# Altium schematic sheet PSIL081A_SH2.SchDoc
size 558 x 431 mm; Date: Not shown in title block; ApprovedBy: Not shown in title block; CheckedBy: Not shown in title block; Author: Not shown in title block; CompanyName: Not shown in title block; Engineer: Not shown in title block; Organization: Not shown in title block; Address1: Not shown in title block; Address2: Not shown in title block; Address3: Not shown in title block; Address4: Not shown in title block; DocumentNumber: 2; Revision: Use project parameter SCH_Rev; SheetNumber: 2; SheetTotal: 5; PageSetup: Record=PageOptions¦CenterHorizontal=True¦CenterVertical=True¦PrintScale=1.00¦XCorrection=1.00¦YCorrection=1.00¦PrintKind=0¦BorderSize=5000000¦LeftOffset=0¦BottomOffset=0¦Orientation=2¦PaperLength=1000¦PaperWidth=1000¦Scale=100¦PaperSource=15¦PrintQuality=600¦MediaType=1¦DitherType=10¦PaperKind=Letter¦PrintScaleMode=1
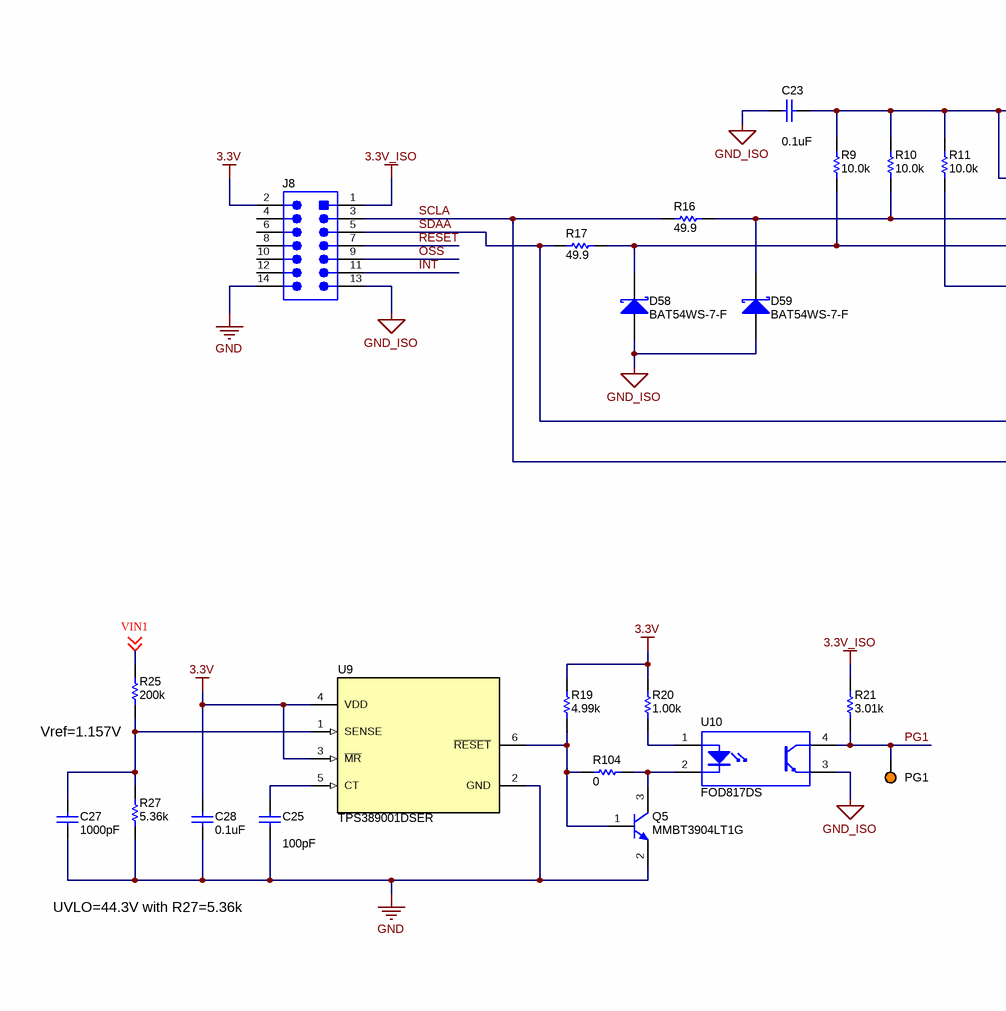
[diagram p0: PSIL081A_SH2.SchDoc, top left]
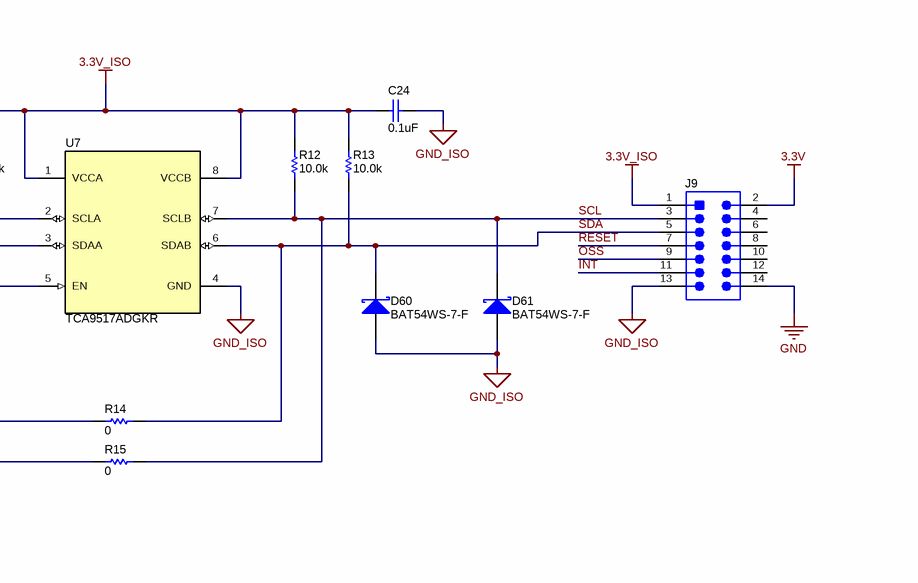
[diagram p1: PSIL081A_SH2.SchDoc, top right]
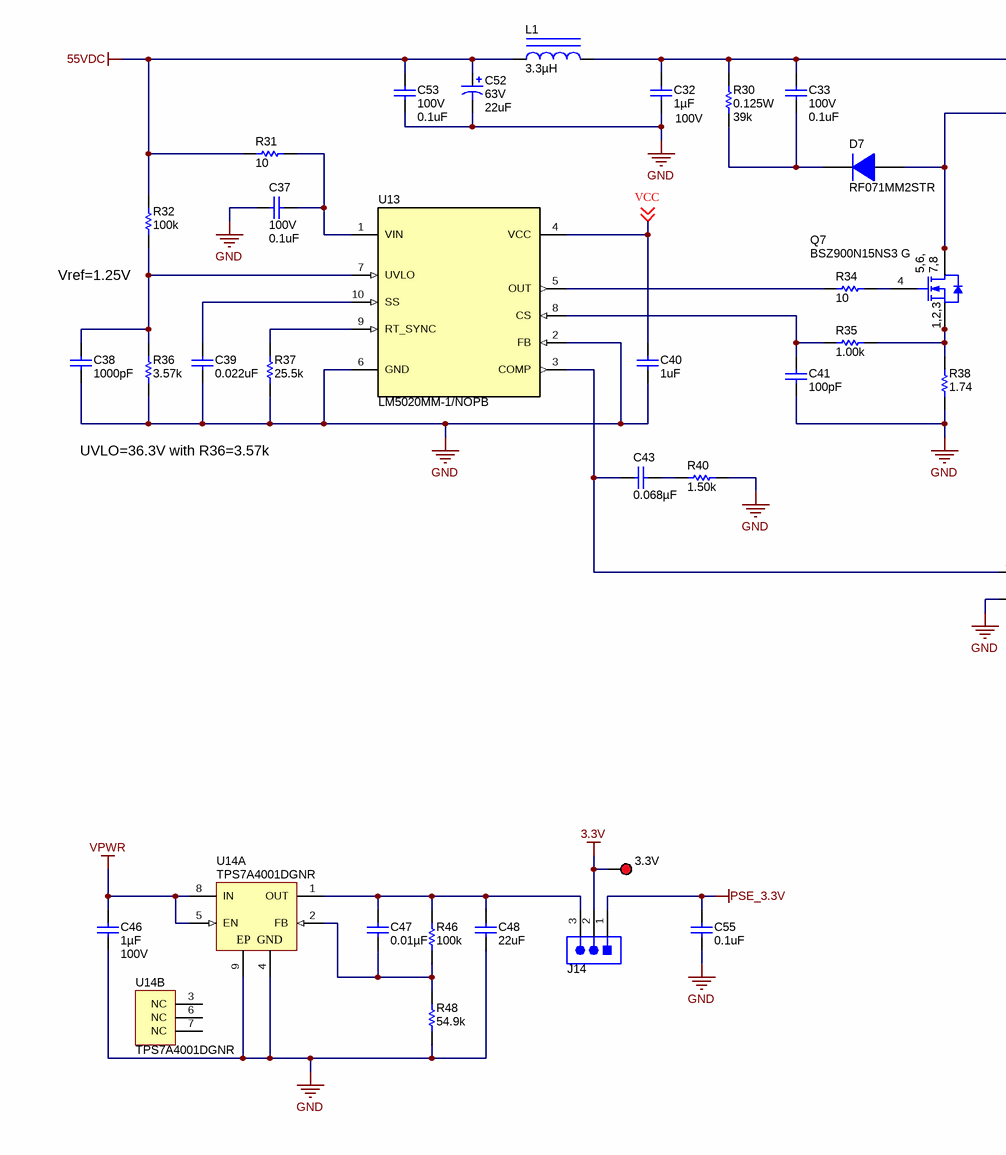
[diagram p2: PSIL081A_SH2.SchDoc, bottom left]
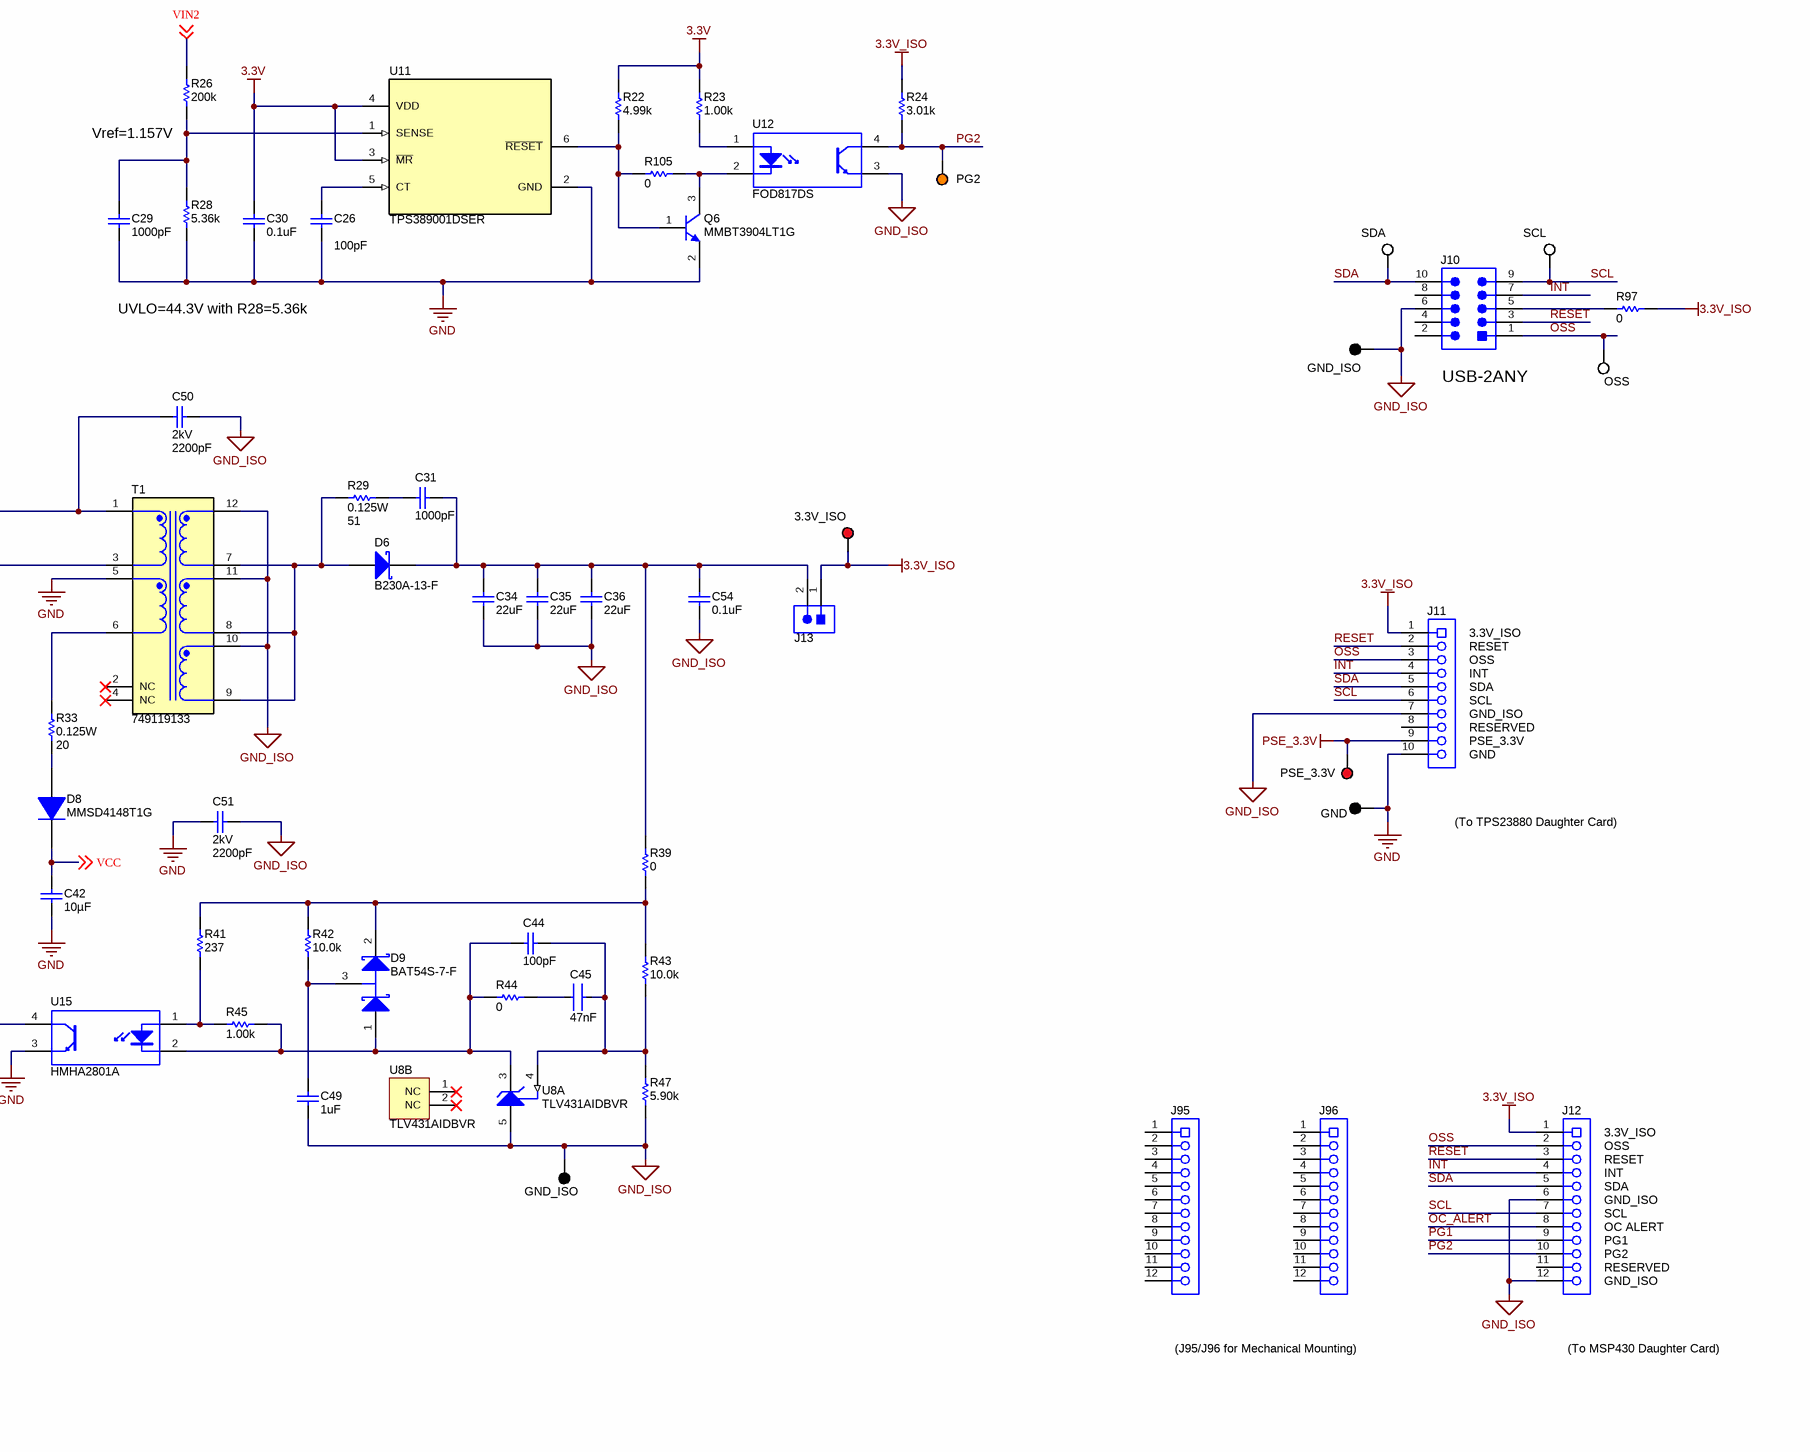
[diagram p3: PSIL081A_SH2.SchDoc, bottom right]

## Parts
C23  ValueDisplayed: 0.1uF  [0603]  (hidden comment: 885012206046)
C24  ValueDisplayed: 0.1uF  [0603]  (hidden comment: 885012206046)
C25  ValueDisplayed: 100pF  [0603]  (hidden comment: 885012006057)
C26  ValueDisplayed: 100pF  [0603]  (hidden comment: 885012006057)
C27  ValueDisplayed: 1000pF  [0402]  (hidden comment: 885012205044)
C28  ValueDisplayed: 0.1uF  [0603]  (hidden comment: 885012206046)
C29  ValueDisplayed: 1000pF  [0402]  (hidden comment: 885012205044)
C30  ValueDisplayed: 0.1uF  [0603]  (hidden comment: 885012206046)
C31  ValueDisplayed: 1000pF  [0603]  (hidden comment: 885012206083)
C32  ValueDisplayed: 1µF  VDC_V: 100V  [1206]  (hidden comment: 12061C105KAT2A)
C33  VDC_V: 100V  ValueDisplayed: 0.1uF  [0805_HV]  (hidden comment: C2012X7R2A104K125AA)
C34  ValueDisplayed: 22uF  [1206]  (hidden comment: JMK316BJ226ML-T)
C35  ValueDisplayed: 22uF  [1206]  (hidden comment: JMK316BJ226ML-T)
C36  ValueDisplayed: 22uF  [1206]  (hidden comment: JMK316BJ226ML-T)
C37  VDC_V: 100V  ValueDisplayed: 0.1uF  [0805_HV]  (hidden comment: C2012X7R2A104K125AA)
C38  ValueDisplayed: 1000pF  [0402]  (hidden comment: 885012205044)
C39  ValueDisplayed: 0.022uF  [0603]  (hidden comment: 885012206091)
C40  ValueDisplayed: 1uF  [0603]  (hidden comment: 885012206052)
C41  ValueDisplayed: 100pF  [0402]  (hidden comment: 885012005061)
C42  ValueDisplayed: 10µF  [1206]  (hidden comment: 885012208041)
C43  ValueDisplayed: 0.068µF  [0603]  (hidden comment: 885012206070)
C44  ValueDisplayed: 100pF  [0402]  (hidden comment: 885012005061)
C45  Cap_F: 47nF  [FP-885012206069_0603-MFG]  (hidden comment: 885012206069)
C46  ValueDisplayed: 1µF  VDC_V: 100V  [1206]  (hidden comment: 12061C105KAT2A)
C47  ValueDisplayed: 0.01µF  [0603]  (hidden comment: 885012206089)
C48  ValueDisplayed: 22uF  [1206]  (hidden comment: JMK316BJ226ML-T)
C49  ValueDisplayed: 1uF  [0603]  (hidden comment: 885012206052)
C50  VDC_V: 2kV  ValueDisplayed: 2200pF  [1812_HV]  (hidden comment: C4532X7R3D222K130KA)
C51  VDC_V: 2kV  ValueDisplayed: 2200pF  [1812_HV]  (hidden comment: C4532X7R3D222K130KA)
C52  VDC_V: 63V  ValueDisplayed: 22uF  [SM_RADIAL_E]  (hidden comment: EEE-FK1J220P)
C53  VDC_V: 100V  ValueDisplayed: 0.1uF  [0805_HV]  (hidden comment: C2012X7R2A104K125AA)
C54  ValueDisplayed: 0.1uF  [0603]  (hidden comment: 885012206046)
C55  ValueDisplayed: 0.1uF  [0603]  (hidden comment: 885012206046)
D6  B230A-13-F  [SMA]
D7  RF071MM2STR  [SOD-123F]
D8  MMSD4148T1G  [SOD-123]
D9  BAT54S-7-F  [SOT-23]
D58  BAT54WS-7-F  [SOD-323]
D59  BAT54WS-7-F  [SOD-323]
D60  BAT54WS-7-F  [SOD-323]
D61  BAT54WS-7-F  [SOD-323]
J8  TST-107-01-G-D  [Samtec_TST-107-01-G-D]  (value not drawn)
J9  TST-107-01-G-D  [Samtec_TST-107-01-G-D]  (value not drawn)
J10  N2510-6002-RB  [CONN_2510-6002]  (value not drawn)
J11  SSW-110-21-G-S  [CONN_SSW-110-23-F-S]  (value not drawn)
J12  SSW-112-21-G-S  [Samtec_SSW-112-21-x-S]  (value not drawn)
J13  TSW-102-07-G-S  [TSW-102-07-G-S]  (value not drawn)
J14  TSW-103-07-G-S  [TSW-103-07-G-S]  (value not drawn)
J95  SSW-112-21-G-S  [Samtec_SSW-112-21-x-S]  (value not drawn)
J96  SSW-112-21-G-S  [Samtec_SSW-112-21-x-S]  (value not drawn)
L1  ValueDisplayed: 3.3µH  [WE-MAPI_2510]  (hidden comment: 74438323033)
Q5  MMBT3904LT1G  [SOT-23]
Q6  MMBT3904LT1G  [SOT-23]
Q7  BSZ900N15NS3 G  [PG-TSDSON-8]
R9  ValueDisplayed: 10.0k  [0402]  (hidden comment: CRCW040210K0FKED)
R10  ValueDisplayed: 10.0k  [0402]  (hidden comment: CRCW040210K0FKED)
R11  ValueDisplayed: 10.0k  [0402]  (hidden comment: CRCW040210K0FKED)
R12  ValueDisplayed: 10.0k  [0402]  (hidden comment: CRCW040210K0FKED)
R13  ValueDisplayed: 10.0k  [0402]  (hidden comment: CRCW040210K0FKED)
R14  ValueDisplayed: 0  [0402]  (hidden comment: ERJ-2GE0R00X)
R15  ValueDisplayed: 0  [0402]  (hidden comment: ERJ-2GE0R00X)
R16  ValueDisplayed: 49.9  [0402]  (hidden comment: CRCW040249R9FKED)
R17  ValueDisplayed: 49.9  [0402]  (hidden comment: CRCW040249R9FKED)
R19  ValueDisplayed: 4.99k  [0402]  (hidden comment: CRCW04024K99FKED)
R20  ValueDisplayed: 1.00k  [0402]  (hidden comment: CRCW04021K00FKED)
R21  ValueDisplayed: 3.01k  [0402]  (hidden comment: CRCW04023K01FKED)
R22  ValueDisplayed: 4.99k  [0402]  (hidden comment: CRCW04024K99FKED)
R23  ValueDisplayed: 1.00k  [0402]  (hidden comment: CRCW04021K00FKED)
R24  ValueDisplayed: 3.01k  [0402]  (hidden comment: CRCW04023K01FKED)
R25  ValueDisplayed: 200k  [0402]  (hidden comment: CRCW0402200KFKED)
R26  ValueDisplayed: 200k  [0402]  (hidden comment: CRCW0402200KFKED)
R27  ValueDisplayed: 5.36k  [0402]  (hidden comment: CRCW04025K36FKED)
R28  ValueDisplayed: 5.36k  [0402]  (hidden comment: CRCW04025K36FKED)
R29  Value2: 0.125W  ValueDisplayed: 51  [0805_HV]  (hidden comment: CRCW080551R0JNEA)
R30  Value2: 0.125W  ValueDisplayed: 39k  [0805_HV]  (hidden comment: CRCW080539K0JNEA)
R31  ValueDisplayed: 10  [0402]  (hidden comment: CRCW040210R0JNED)
R32  ValueDisplayed: 100k  [0402]  (hidden comment: CRCW0402100KFKED)
R33  Value2: 0.125W  ValueDisplayed: 20  [0805_HV]  (hidden comment: CRCW080520R0JNEA)
R34  ValueDisplayed: 10  [0402]  (hidden comment: CRCW040210R0JNED)
R35  ValueDisplayed: 1.00k  [0402]  (hidden comment: CRCW04021K00FKED)
R36  ValueDisplayed: 3.57k  [0402]  (hidden comment: CRCW04023K57FKED)
R37  ValueDisplayed: 25.5k  [0402]  (hidden comment: CRCW040225K5FKED)
R38  ValueDisplayed: 1.74  [0603]  (hidden comment: CRCW06031R74FKEA)
R39  ValueDisplayed: 0  [0402]  (hidden comment: ERJ-2GE0R00X)
R40  ValueDisplayed: 1.50k  [0402]  (hidden comment: CRCW04021K50FKED)
R41  ValueDisplayed: 237  [0402]  (hidden comment: CRCW0402237RFKED)
R42  ValueDisplayed: 10.0k  [0402]  (hidden comment: CRCW040210K0FKED)
R43  ValueDisplayed: 10.0k  [0402]  (hidden comment: CRCW040210K0FKED)
R44  ValueDisplayed: 0  [0402]  (hidden comment: ERJ-2GE0R00X)
R45  ValueDisplayed: 1.00k  [0402]  (hidden comment: CRCW04021K00FKED)
R46  ValueDisplayed: 100k  [0402]  (hidden comment: CRCW0402100KFKED)
R47  ValueDisplayed: 5.90k  [0402]  (hidden comment: CRCW04025K90FKED)
R48  ValueDisplayed: 54.9k  [0402]  (hidden comment: CRCW040254K9FKED)
R97  ValueDisplayed: 0  [0402]  (hidden comment: ERJ-2GE0R00X)
R104  ValueDisplayed: 0  [0402]  (hidden comment: ERJ-2GE0R00X)
R105  ValueDisplayed: 0  [0402]  (hidden comment: ERJ-2GE0R00X)
T1  749119133  [Wurth_EP11_5]
TP4  SDA  [Keystone5002]
TP5  SCL  [Keystone5002]
TP6  PG1  [Keystone5003]
TP7  PG2  [Keystone5003]
TP8  PSE_3.3V  [Keystone5000]
TP9  GND  [Keystone5001]
TP10  3.3V_ISO  [Keystone5000]
TP11  3.3V  [Keystone5000]
TP12  GND_ISO  [Keystone5001]
TP13  GND_ISO  [Keystone5001]
TP14  OSS  [Keystone5002]
U7  TCA9517ADGKR  [DGK0008A_N]
U8  TLV431AIDBVR  [DBV0005A_N]  (parts A,B of 2)
U9  TPS389001DSER  [DSE0006A]
U10  FOD817DS  [N04C]
U11  TPS389001DSER  [DSE0006A]
U12  FOD817DS  [N04C]
U13  LM5020MM-1/NOPB  [DGS0010A_N]
U14  TPS7A4001DGNR  [DGN0008B_N]  (parts A,B of 2)
U15  HMHA2801A  [MFP04A]

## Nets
3.3V: C28.2 C30.2 J8.2 J9.2 J14.2 R19.1 R20.1 R22.1 R23.1 TP11.1 U9.3(~{MR}) U9.4(VDD) U11.3(~{MR}) U11.4(VDD)
3.3V_ISO: C23.1 C24.1 J8.1 J9.1 J11.1 J12.1 J13.1 R9.1 R10.1 R11.1 R12.1 R13.1 R21.1 R24.1 R97.1 TP10.1 U7.1(VCCA) U7.8(VCCB)
55VDC: C52.1(+) C53.2 L1.1 R31.1 R32.1
GND: C25.1 C26.1 C27.1 C28.1 C29.1 C30.1 C32.1 C37.2 C38.1 C39.1 C40.1 C41.1 C42.1 C46.2 C48.2 C51.2 C52.2(-) C53.1 C55.1 J8.14 J9.14 J11.10 Q5.2(E) Q6.2(E) R27.2 R28.2 R36.2 R37.2 R38.2 R40.2 R48.2 T1.5 TP9.1 U9.2(GND) U11.2(GND) U13.2(FB) U13.6(GND) U14.4(GND) U14.9(EP) U15.3(E)
GND_ISO: C23.2 C24.2 C34.1 C35.1 C36.1 C49.1 C50.1 C51.1 C54.1 D58.2(A) D59.2(A) D60.2(A) D61.2(A) J8.13 J9.13 J10.6 J11.7 J12.6 J12.12 R47.2 T1.10 T1.11 T1.12 TP12.1 TP13.1 U7.4(GND) U8.5(ANODE) U10.3(E) U12.3(E)
PSE_3.3V: C55.2 J11.9 J14.1 TP8.1
VPWR: C46.1 U14.5(EN) U14.8(IN)
INT: J8.11 J9.11 J10.7 J11.4 J12.4
OC_ALERT: J12.8
OSS: J8.9 J9.9 J10.1 J11.3 J12.2 TP14.1
PG1: J12.9 R21.2 TP6.1 U10.4(C)
PG2: J12.10 R24.2 TP7.1 U12.4(C)
RESET: J8.7 J9.7 J10.3 J11.2 J12.3
SCL: D61.1(K) J9.3 J10.9 J11.6 J12.7 R12.2 R15.1 TP5.1 U7.7(SCLB)
SCLA: J8.3 R15.2 R16.1
SDA: D60.1(K) J9.5 J10.10 J11.5 J12.5 R13.2 R14.1 TP4.1 U7.6(SDAB)
SDAA: J8.5 R14.2 R17.1
VCC: C40.2 C42.2 D8.1(K) U13.4(VCC) ; off-sheet VCC
VIN1: R25.1 ; off-sheet VIN1
VIN2: R26.1 ; off-sheet VIN2
NetC25_2: C25.2 U9.5(CT)
NetC26_2: C26.2 U11.5(CT)
NetC27_2: C27.2 R25.2 R27.1 U9.1(SENSE)
NetC29_2: C29.2 R26.2 R28.1 U11.1(SENSE)
NetC31_1: C31.1 C34.2 C35.2 C36.2 C54.2 D6.1(K) J13.2 R39.2
NetC31_2: C31.2 R29.2
NetC32_2: C32.2 C33.2 C50.2 L1.2 R30.1 T1.1
NetC33_1: C33.1 D7.1(K) R30.2
NetC37_1: C37.1 R31.2 U13.1(VIN)
NetC38_2: C38.2 R32.2 R36.1 U13.7(UVLO)
NetC39_2: C39.2 U13.10(SS)
NetC41_2: C41.2 R35.1 U13.8(CS)
NetC43_1: C43.1 R40.1
NetC43_2: C43.2 U13.3(COMP) U15.4(C)
NetC44_1: C44.1 C45.1 R43.2 R47.1 U8.4(REF)
NetC44_2: C44.2 D9.1(A) R44.2 R45.1 U8.3(CATHODE) U15.2(K)
NetC45_2: C45.2 R44.1
NetC47_1: C47.1 C48.1 J14.3 R46.1 U14.1(OUT)
NetC47_2: C47.2 R46.2 R48.1 U14.2(FB)
NetC49_2: C49.2 D9.3(C) R42.2
NetD6_2: D6.2(A) R29.1 T1.7 T1.8 T1.9
NetD7_2: D7.2(A) Q7.5(D) Q7.6(D) Q7.7(D) Q7.8(D) Q7.9(D) T1.3
NetD8_2: D8.2(A) R33.2
NetD9_2: D9.2(K) R39.1 R41.1 R42.1 R43.1
NetD58_1: D58.1(K) R9.2 R17.2 U7.3(SDAA)
NetD59_1: D59.1(K) R10.2 R16.2 U7.2(SCLA)
NetJ10_5: J10.5 R97.2
NetQ5_1: Q5.1(B) R19.2 R104.2 U9.6(~{RESET})
NetQ5_3: Q5.3(C) R104.1 U10.2(K)
NetQ6_1: Q6.1(B) R22.2 R105.2 U11.6(~{RESET})
NetQ6_3: Q6.3(C) R105.1 U12.2(K)
NetQ7_1: Q7.1(S) Q7.2(S) Q7.3(S) R35.2 R38.1
NetQ7_4: Q7.4(G) R34.2
NetR11_2: R11.2 U7.5(EN)
NetR20_2: R20.2 U10.1(A)
NetR23_2: R23.2 U12.1(A)
NetR33_1: R33.1 T1.6
NetR34_1: R34.1 U13.5(OUT)
NetR37_1: R37.1 U13.9(RT_SYNC)
NetR41_2: R41.2 R45.2 U15.1(A)

Not connected (* = marked no-connect by the designer): J8 4 6 8 10 12; J9 4 6 8 10 12; J10 2 4 8; J11 8; J12 11; J95 1 2 3 4 5 6 7 8 9 10 11 12; J96 1 2 3 4 5 6 7 8 9 10 11 12; T1 2(NC)* 4(NC)*; U8 1(NC)* 2(NC)*; U14 3(NC) 6(NC) 7(NC)

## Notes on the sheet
- (near R25) Vref=1.157V
- (near R26) Vref=1.157V
- UVLO=44.3V with R27=5.36k
- UVLO=44.3V with R28=5.36k
- (near J10) USB-2ANY
- (near J11) 3.3V_ISO
- (near J11) RESET
- (near J11) OSS
- (near J11) INT
- (near J11) SDA
- (near J11) SCL
- (near R32) Vref=1.25V
- (near J11) RESERVED
- (near J11) GND_ISO
- (near J11) PSE_3.3V
- (near J11) GND
- (To TPS23880 Daughter Card)
- UVLO=36.3V with R36=3.57k
- (near J12) 3.3V_ISO
- (near J12) OSS
- (near J12) RESET
- (near J12) INT
- (near J12) SDA
- (near J12) GND_ISO
- (near J12) SCL
- (near J12) OC ALERT
- (near J12) PG1
- (near J12) PG2
- (near J12) RESERVED
- (J95/J96 for Mechanical Mounting)
- (To MSP430 Daughter Card)

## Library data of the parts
C23 C24 C28 C30 C54 C55 = CMP-0006829-4: CAP, CERM, 0.1 uF, 16 V, +/- 10%, X7R, 0603; Manufacturer: Wurth Elektronik; TaMin_C: -55°C; Polarized: N; SizeAreaWB_mm2: 4.68; Value1: Unknown; U/M: EA; Value: 0.1uF; TaMax_C: 125°C; SizeZ_mm: 1; SizeX_mm: 1.6; SizeY_mm: 0.8; Value2: 16V; SizeArea_mm2: 1.28; CompType: Capacitor; Cap_F: 100nF; AEC Category: Q200
C25 C26 = CMP-0006822-4: CAP, CERM, 100 pF, 50 V, +/- 5%, C0G/NP0, 0603; Manufacturer: Wurth Elektronik; TaMin_C: -55°C; Polarized: N; SizeAreaWB_mm2: 4.68; Value1: Unknown; U/M: EA; Value: 100pF; TaMax_C: 125°C; SizeZ_mm: 1; SizeX_mm: 1.6; SizeY_mm: 0.8; Value2: 50V; SizeArea_mm2: 1.28; CompType: Capacitor; AEC Category: Q200
C27 C29 C38 = CMP-0006229-2: CAP, CERM, 1000 pF, 25 V, +/- 10%, X7R, 0402; Manufacturer: Wurth Elektronik; TaMin_C: -55°C; Polarized: N; SizeAreaWB_mm2: 3; Value1: Unknown; U/M: EA; Value: 1000pF; TaMax_C: 125°C; SizeZ_mm: 0.6; SizeX_mm: 1; SizeY_mm: 0.5; Value2: 25V; CompType: Capacitor; Cap_F: 1nF; AEC Category: Q200
C31 = CMP-0064933-4: CAP, CERM, 1000 pF, 50 V,+/- 10%, X7R, 0603; Manufacturer: Wurth Elektronik; TaMin_C: -55°C; Polarized: N; SizeAreaWB_mm2: 4.68; Value1: Unknown; U/M: EA; Value: 1000pF; TaMax_C: 125°C; SizeZ_mm: 1; SizeX_mm: 1.6; SizeY_mm: 0.8; Value2: 50V; SizeArea_mm2: 1.28; CompType: Capacitor; Cap_F: 1nF; AEC Category: Q200
C32 C46 = CMP-0750068-1: CAP, CERM, 1 µF, 100 V,+/- 10%, X7R, 1206; Manufacturer: AVX; SizeY_mm: 1.6; CompType: Capacitor; SizeAreaWB_mm2: 10.92; AEC Qualified: N; TaMin_C: -55°C; SizeX_mm: 3.2; SizeZ_mm: 1.35; U/M: EA; AEC Category: Q200; TaMax_C: 125°C; Value: 1uF; SizeArea_mm2: 5.12
C33 C37 C53 = CMP-0007886-2: CAP, CERM, 0.1 uF, 100 V, +/- 10%, X7R, 0805; Manufacturer: TDK; TaMin_C: -55°C; ESR_ohm: 0.020726; Polarized: N; SizeAreaWB_mm2: 6.75; Value1: 0.020726 ohm; U/M: EA; Value: 0.1uF; TaMax_C: 125°C; SizeZ_mm: 1.45; SizeX_mm: 2; SizeY_mm: 1.25; Cap_Case: 0805; SizeArea_mm2: 2.5; Cap_F: 100nF; IRMS_A: 1.456A; AEC Category: Q200
C34-C36 C48 = CMP-0009020-2: CAP, CERM, 22 uF, 6.3 V, +/- 20%, X5R, 1206; Manufacturer: Taiyo Yuden; TaMin_C: -55°C; ESR_ohm: 0.012; Polarized: N; SizeAreaWB_mm2: 10.92; Value1: 0.012 ohm; U/M: EA; Value: 22uF; TaMax_C: 125°C; SizeZ_mm: 1.35; SizeX_mm: 3.2; SizeY_mm: 1.6; Value2: 6.3V; SizeArea_mm2: 5.12; CompType: Capacitor; Cap_F: 22µF; AEC Category: Q200
C39 = CMP-0006836-4: CAP, CERM, 0.022 uF, 50 V, +/- 10%, X7R, 0603; Manufacturer: Wurth Elektronik; TaMin_C: -55°C; Polarized: N; SizeAreaWB_mm2: 4.68; Value1: Unknown; U/M: EA; TaMax_C: 125°C; SizeZ_mm: 1; SizeX_mm: 1.6; SizeY_mm: 0.8; Value2: 50V; SizeArea_mm2: 1.28; CompType: Capacitor; Cap_F: 22nF; AEC Category: Q200
C40 C49 = CMP-0006831-4: CAP, CERM, 1 uF, 16 V, +/- 10%, X7R, 0603; Manufacturer: Wurth Elektronik; TaMin_C: -55°C; Polarized: N; SizeAreaWB_mm2: 4.68; Value1: Unknown; U/M: EA; Value: 1uF; TaMax_C: 125°C; SizeZ_mm: 1; SizeX_mm: 1.6; SizeY_mm: 0.8; Value2: 16V; SizeArea_mm2: 1.28; CompType: Capacitor; Cap_F: 1µF; AEC Category: Q200
C41 C44 = CMP-0006217-2: CAP, CERM, 100 pF, 50 V, +/- 5%, C0G/NP0, 0402; Manufacturer: Wurth Elektronik; TaMin_C: -55°C; Polarized: N; SizeAreaWB_mm2: 3; Value1: Unknown; U/M: EA; Value: 100pF; TaMax_C: 125°C; SizeZ_mm: 0.6; SizeX_mm: 1; SizeY_mm: 0.5; Value2: 50V; CompType: Capacitor; AEC Category: Q200
C42 = CMP-0750070-1: CAP, CERM, 10 µF, 16 V,+/- 10%, X7R, 1206; Manufacturer: Wurth Elektronik; SizeArea_mm2: 5.12; SizeZ_mm: 1.35; Polarized: N; SizeAreaWB_mm2: 10.92; AEC Category: Q200; CompType: Capacitor; SizeX_mm: 3.2; TaMin_C: -55°C; U/M: EA; TaMax_C: 125°C; Value: 10uF; Value2: 16V; SizeY_mm: 1.6
C43 = CMP-0750069-1: CAP, CERM, 0.068 µF, 25 V,+/- 10%, X7R, 0603; Manufacturer: Wurth Elektronik; SizeAreaWB_mm2: 4.68; U/M: EA; SizeArea_mm2: 1.28; TaMin_C: -55°C; Value: 0.068uF; SizeY_mm: 0.8; SizeX_mm: 1.6; CompType: Capacitor; AEC Category: Q200; VDC_V: 25V; AEC Qualified: N; Cap_F: 68nF; SizeZ_mm: 1; TaMax_C: 125°C
C45 = CMP-0086483-1: 0.047µF ±10% 25V Ceramic Capacitor X7R 0603 (1608 Metric); Manufacturer: Wurth Electronics; SizeZ_mm: 0.95mm; TempCo: 15%; Symbol Name: SYM-885012206069; AEC Qualified: No
C47 = CMP-0750039-1: CAP, CERM, 0.01 µF, 50 V,+/- 10%, X7R, 0603; Manufacturer: Wurth Elektronik; Polarized: N; AEC Category: Q200; TaMax_C: 125°C; SizeAreaWB_mm2: 4.68; Value: 0.01uF; CompType: Capacitor; SizeArea_mm2: 1.28; SizeY_mm: 0.8; SizeZ_mm: 1; SizeX_mm: 1.6; VDC_V: 50V; U/M: EA; Cap_F: 10nF; TaMin_C: -55°C
C50 C51 = CMP-0009358-2: CAP, CERM, 2200 pF, 2000 V, +/- 10%, X7R, 1812; Manufacturer: TDK; TaMin_C: -55°C; Polarized: N; SizeAreaWB_mm2: 23.1; Value1: Unknown; U/M: EA; Value: 2200pF; TaMax_C: 125°C; SizeZ_mm: 1.35; SizeX_mm: 4.5; SizeY_mm: 3.2; Cap_Case: 1812; Value2: 2000V; SizeArea_mm2: 14.4; CompType: Capacitor; Cap_F: 2.2nF; AEC Category: Q200
C52 = CMP-0011189-2: CAP, AL, 22 uF, 63 V, +/- 20%, 1.2 ohm, AEC-Q200 Grade 2, SMD; Manufacturer: Panasonic; TaMin_C: -55°C; ESR_ohm: 1.2; Polarized: Y; SizeAreaWB_mm2: 118.45; Value1: 1.2 ohm; U/M: EA; Value: 22uF; TaMax_C: 105°C; SizeZ_mm: 6.2; SizeX_mm: 9.5; SizeY_mm: 8.3; Cap_Case: E; SizeArea_mm2: 78.85; CompType: Capacitor; Cap_F: 22µF; IRMS_A: 1.2dA; AEC Grade: 2; AEC Category: Q200
D6 = CMP-0028401-1: Diode, Schottky, 30 V, 2 A, SMA; Manufacturer: Diodes Inc.; Io_A: 2A; Green_Lifecycle: Active; SizeAreaWB_mm2: 37.3428; Vr_V: 30V; Green_REACh: Passed; TJmax_C: 150°C; U/M: EA; Value: 30V; SizeZ_mm: 2.87; SizeX_mm: 5.59; SizeY_mm: 2.92; Vf_V: 5dV; Value2: 0.5V; SizeArea_mm2: 16.3228; AEC Category: Q101; RJC_CperW: 20
D7 = CMP-0750076-1: Diode, Superfast Rectifier, 200 V, 0.7 A, SOD-123F; Manufacturer: Rohm; SizeX_mm: 3.5; Vr_V: 200V; Value2: 0.85V; SizeY_mm: 1.6; Io_A: 7dA; SizeAreaWB_mm2: 11.7; Value: 200V; AEC Category: Q101; Value1: 0.7A; SizeArea_mm2: 5.6; SizeZ_mm: 1.1; Vf_V: 8.5dV; AEC Qualified: N; TJmax_C: 150°C
D8 = CMP-0029032-1: Diode, Switching, 100 V, 0.2 A, SOD-123; Manufacturer: ON Semiconductor; Io_A: 2dA; Green_Lifecycle: Active; SizeAreaWB_mm2: 13.095; Vr_V: 100V; Green_REACh: Passed; Value1: 0.2A; TJmax_C: 150°C; U/M: EA; Value: 100V; SizeZ_mm: 1.35; SizeX_mm: 3.85; SizeY_mm: 1.7; Vf_V: 1V; SizeArea_mm2: 6.545; AEC Category: Q101
D9 = CMP-0028456-1: Diode, Schottky, 30 V, 0.2 A, SOT-23; Manufacturer: Diodes Inc.; Io_A: 2dA; Green_Lifecycle: Active; SizeAreaWB_mm2: 14; Vr_V: 30V; Green_REACh: Passed; Value1: 0.2A; TJmax_C: 125°C; U/M: EA; Value: 30V; SizeZ_mm: 1.1; SizeX_mm: 2.5; SizeY_mm: 3; Vf_V: 6.5dV; Value2: 0.65V; SizeArea_mm2: 7.5; AEC Category: Q101
D58-D61 = CMP-0028458-2: Diode, Schottky, 30 V, 0.2 A, SOD-323; Manufacturer: Diodes Inc.; SizeArea_mm2: 3.645; Green_Lifecycle: Active; Io_A: 200mA; TJmax_C: 125°C; Value2: 0.7V; Vf_V: 700mV; Green_REACh: Passed; Value1: 0.2A; Vr_V: 30V; AEC Category: Q101; SizeAreaWB_mm2: 8.695; SizeY_mm: 1.35; Value: 30V; SizeX_mm: 2.7; SizeZ_mm: 1
J8 J9 = CMP-0078831-2: Header(shrouded), 2.54mm, 7x2, Gold, TH; Manufacturer: Samtec; Pitch_mm: 2.54; Gender: Male; Cert_UL: Y; Voltage_V: 1kV; Current_A: 3.4A; Row_Count: 2
J10 = CMP-0055448-2: Header (shrouded), 100mil, 5x2, High-Temperature, Gold, TH; Manufacturer: 3M; Green_Lifecycle: Active; Green_REACh: Passed
J11 = CMP-0750079-1: Receptacle, 2.54mm, 10x1, Gold, TH; Manufacturer: Samtec; Current_A: 4.7A; Gender: Female; Cert_UL: Y; Row_Count: 1; Voltage_V: 655V; Pitch_mm: 2.54
J12 J95 J96 = CMP-0750078-1: Receptacle, 2.54mm, 12x1, Gold, TH; Manufacturer: Samtec; Pitch_mm: 2.54; Voltage_V: 655V; Gender: Female; Current_A: 4.7A; Row_Count: 1; Cert_UL: Y
J13 = CMP-0075405-2: Header, 100mil, 2x1, Gold, TH; Manufacturer: Samtec; Pitch_mm: 2.54; Cert_VDE: N; Gender: Male; Cert_CSA: Y; Voltage_V: 550V; Green_REACh: Passed; Current_A: 6.3A; Green_Lifecycle: Active; Row_Count: 1
J14 = CMP-0075407-2: Header, 100mil, 3x1, Gold, TH; Manufacturer: Samtec; Pitch_mm: 2.54; Cert_VDE: N; Gender: Male; Cert_CSA: Y; Voltage_V: 550V; Green_REACh: Passed; Current_A: 6.3A; Green_Lifecycle: Active; Row_Count: 1
L1 = CMP-0750073-1: Inductor, Shielded, Metal Composite, 3.3 µH, 1.25 A, 0.264 ohm, SMD; Manufacturer: Wurth Elektronik; Value2: 1.25A; SizeZ_mm: 1; Irms: 1.25A @ 40C rise; SizeArea_mm2: 5; DCR_ohm: 2.64d; SizeY_mm: 2; Isat: 2.1A @ 20% inductance drop; SizeX_mm: 2.5; Value: 3.3uH; AEC Category: Q200; AEC Qualified: N; SizeAreaWB_mm2: 10.5
Q5 Q6 = CMP-0000419-2: Transistor, NPN, 40 V, 0.2 A, SOT-23; Manufacturer: ON Semiconductor; TaMax_C: 150°C; Value2: 300; Value1: 0.2 A; Vcesat1_V: 3dV; SizeX_mm: 2.5; SizeY_mm: 3; TaMin_C: -55°C; IcRated_A: 2dA; CompType: BJT; SizeZ_mm: 1.1; Value: 40 V; SizeArea_mm2: 7.5; NPN: 1; Vceo_V: 40V; PNP: 0; AEC Category: Q101; SizeAreaWB_mm2: 14; U/M: EA
Q7 = CMP-0001051-2: MOSFET, N-CH, 150 V, 13 A, PG-TSDSON-8; Alternate Manufacturer: None; Manufacturer: Infineon Technologies; SizeZ_mm: 1.1; ChType: N; Value2: 5 nC; VdsMax_V: 150V; SizeX_mm: 3.4; Vgs_V: 20V; QgTyp_nC: 5; Value: 150V; SizeArea_mm2: 11.56; AEC Category: Q101; IdsMax_A: 13A; SizeAreaWB_mm2: 19.36; U/M: EA
R9-R13 R42 R43 = CMP-0025958-3: RES, 10.0 k, 1%, 0.063 W, AEC-Q200 Grade 0, 0402; Manufacturer: Vishay-Dale; Power_W: 63mW; TempCo: 100 ppm/C; Value_Code: 10k0; Value: 10.0k; EIA_Code: E96; Res_ohm: 10k; SizeX_mm: 1; SizeY_mm: 0.5; SizeZ_mm: 0.6; Value2: 0.063W; AEC Qualified: Y; VDC_V: 50V; AEC Category: Q200; AEC Grade: 0
R14 R15 R39 R44 R97 = CMP-0026992-3: RES, 0, 5%, 0.1 W, AEC-Q200 Grade 0, 0402; Manufacturer: Panasonic; Power_W: 100mW; TempCo: 600 ppm/C; Value_Code: 0000; Value: 0; EIA_Code: E24; SizeX_mm: 1; SizeY_mm: 0.5; SizeZ_mm: 0.6; Value2: 0.1W; AEC Qualified: Y; VDC_V: 50V; AEC Category: Q200; SizeAreaWB_mm2: 3
R16 R17 = CMP-0026404-2: RES, 49.9, 1%, 0.063 W, AEC-Q200 Grade 0, 0402; Manufacturer: Vishay-Dale; Power_W: 63mW; TempCo: 100 ppm/C; Value_Code: 49R9; Value: 49.9; EIA_Code: E96; SizeX_mm: 1; SizeY_mm: 0.5; SizeZ_mm: 0.6; Value2: 0.063W; AEC Qualified: Y; VDC_V: 50V; AEC Category: Q200; AEC Grade: 0
R19 R22 = CMP-0026414-2: RES, 4.99 k, 1%, 0.063 W, AEC-Q200 Grade 0, 0402; Manufacturer: Vishay-Dale; Power_W: 63mW; TempCo: 100 ppm/C; Value_Code: 4k99; Value: 4.99k; EIA_Code: E96; SizeX_mm: 1; SizeY_mm: 0.5; SizeZ_mm: 0.6; Value2: 0.063W; AEC Qualified: Y; VDC_V: 50V; AEC Category: Q200; AEC Grade: 0
R20 R23 R35 R45 = CMP-0026071-3: RES, 1.00 k, 1%, 0.063 W, AEC-Q200 Grade 0, 0402; Manufacturer: Vishay-Dale; Power_W: 63mW; TempCo: 100 ppm/C; Value_Code: 1k00; Value: 1.00k; EIA_Code: E96; Res_ohm: 1k; SizeX_mm: 1; SizeY_mm: 0.5; SizeZ_mm: 0.6; Value2: 0.063W; AEC Qualified: Y; VDC_V: 50V; AEC Category: Q200; AEC Grade: 0
R21 R24 = CMP-0026329-2: RES, 3.01 k, 1%, 0.063 W, AEC-Q200 Grade 0, 0402; Manufacturer: Vishay-Dale; Power_W: 63mW; TempCo: 100 ppm/C; Value_Code: 3k01; Value: 3.01k; EIA_Code: E96; SizeX_mm: 1; SizeY_mm: 0.5; SizeZ_mm: 0.6; Value2: 0.063W; AEC Qualified: Y; VDC_V: 50V; AEC Category: Q200; AEC Grade: 0
R25 R26 = CMP-0026158-2: RES, 200 k, 1%, 0.063 W, AEC-Q200 Grade 0, 0402; Manufacturer: Vishay-Dale; Power_W: 63mW; TempCo: 100 ppm/C; Value: 200k; EIA_Code: E96; SizeX_mm: 1; SizeY_mm: 0.5; SizeZ_mm: 0.6; Value2: 0.063W; AEC Qualified: Y; VDC_V: 50V; AEC Category: Q200; AEC Grade: 0
R27 R28 = CMP-0026465-2: RES, 5.36 k, 1%, 0.063 W, AEC-Q200 Grade 0, 0402; Manufacturer: Vishay-Dale; Power_W: 63mW; TempCo: 100 ppm/C; Value_Code: 5k36; Value: 5.36k; EIA_Code: E96; SizeX_mm: 1; SizeY_mm: 0.5; SizeZ_mm: 0.6; Value2: 0.063W; AEC Qualified: Y; VDC_V: 50V; AEC Category: Q200; AEC Grade: 0
R29 = CMP-0020567-3: RES, 51, 5%, 0.125 W, AEC-Q200 Grade 0, 0805; Manufacturer: Vishay-Dale; Power_W: 125mW; TempCo: 200 ppm/C; Value_Code: 51R0; Value: 51; EIA_Code: E24; SizeX_mm: 2; SizeY_mm: 1.25; SizeZ_mm: 1.45; SizeArea_mm2: 2.5; CompType: Resistor; AEC Qualified: Y; VDC_V: 150V; AEC Category: Q200; AEC Grade: 0
R30 = CMP-0020536-3: RES, 39 k, 5%, 0.125 W, AEC-Q200 Grade 0, 0805; Manufacturer: Vishay-Dale; Power_W: 125mW; TempCo: 200 ppm/C; Value_Code: 39k0; Value: 39k; EIA_Code: E24; SizeX_mm: 2; SizeY_mm: 1.25; SizeZ_mm: 1.45; SizeArea_mm2: 2.5; CompType: Resistor; AEC Qualified: Y; VDC_V: 150V; AEC Category: Q200; AEC Grade: 0
R31 R34 = CMP-0026827-3: RES, 10, 5%, 0.063 W, AEC-Q200 Grade 0, 0402; Manufacturer: Vishay-Dale; Power_W: 63mW; TempCo: 200 ppm/C; Value_Code: 10R0; Value: 10; EIA_Code: E24; SizeX_mm: 1; SizeY_mm: 0.5; SizeZ_mm: 0.6; Value2: 0.063W; AEC Qualified: Y; VDC_V: 50V; AEC Category: Q200; AEC Grade: 0
R32 R46 = CMP-0025950-3: RES, 100 k, 1%, 0.063 W, AEC-Q200 Grade 0, 0402; Manufacturer: Vishay-Dale; Power_W: 63mW; TempCo: 100 ppm/C; Value: 100k; EIA_Code: E96; SizeX_mm: 1; SizeY_mm: 0.5; SizeZ_mm: 0.6; Value2: 0.063W; AEC Qualified: Y; VDC_V: 50V; AEC Category: Q200; AEC Grade: 0
R33 = CMP-0020497-3: RES, 20, 5%, 0.125 W, AEC-Q200 Grade 0, 0805; Manufacturer: Vishay-Dale; Power_W: 125mW; TempCo: 200 ppm/C; Value_Code: 20R0; Value: 20; EIA_Code: E24; SizeX_mm: 2; SizeY_mm: 1.25; SizeZ_mm: 1.45; SizeArea_mm2: 2.5; CompType: Resistor; AEC Qualified: Y; VDC_V: 150V; AEC Category: Q200; AEC Grade: 0
R36 = CMP-0026336-2: RES, 3.57 k, 1%, 0.063 W, AEC-Q200 Grade 0, 0402; Manufacturer: Vishay-Dale; Power_W: 63mW; TempCo: 100 ppm/C; Value_Code: 3k57; Value: 3.57k; EIA_Code: E96; SizeX_mm: 1; SizeY_mm: 0.5; SizeZ_mm: 0.6; Value2: 0.063W; AEC Qualified: Y; VDC_V: 50V; AEC Category: Q200; AEC Grade: 0
R37 = CMP-0026201-2: RES, 25.5 k, 1%, 0.063 W, AEC-Q200 Grade 0, 0402; Manufacturer: Vishay-Dale; Power_W: 63mW; TempCo: 100 ppm/C; Value_Code: 25k5; Value: 25.5k; EIA_Code: E96; SizeX_mm: 1; SizeY_mm: 0.5; SizeZ_mm: 0.6; Value2: 0.063W; AEC Qualified: Y; VDC_V: 50V; AEC Category: Q200; AEC Grade: 0
R38 = CMP-0022193-4: RES, 1.74, 1%, 0.1 W, AEC-Q200 Grade 0, 0603; Manufacturer: Vishay-Dale; Power_W: 100mW; TempCo: 100 ppm/C; Value_Code: 1R74; Value: 1.74; EIA_Code: E96; SizeX_mm: 1.6; SizeY_mm: 0.8; SizeZ_mm: 1; Value2: 0.1W; SizeArea_mm2: 1.28; AEC Qualified: Y; VDC_V: 75V; AEC Category: Q200; AEC Grade: 0
R40 = CMP-0026088-3: RES, 1.50 k, 1%, 0.063 W, AEC-Q200 Grade 0, 0402; Manufacturer: Vishay-Dale; Power_W: 63mW; TempCo: 100 ppm/C; Value_Code: 1k50; Value: 1.50k; EIA_Code: E96; Res_ohm: 1.5k; SizeX_mm: 1; SizeY_mm: 0.5; SizeZ_mm: 0.6; Value2: 0.063W; AEC Qualified: Y; VDC_V: 50V; AEC Category: Q200; AEC Grade: 0
R41 = CMP-0026185-2: RES, 237, 1%, 0.063 W, AEC-Q200 Grade 0, 0402; Manufacturer: Vishay-Dale; Power_W: 63mW; TempCo: 100 ppm/C; Value_Code: 237R; Value: 237; EIA_Code: E96; SizeX_mm: 1; SizeY_mm: 0.5; SizeZ_mm: 0.6; Value2: 0.063W; AEC Qualified: Y; VDC_V: 50V; AEC Category: Q200; AEC Grade: 0
R47 = CMP-0026469-2: RES, 5.90 k, 1%, 0.063 W, AEC-Q200 Grade 0, 0402; Manufacturer: Vishay-Dale; Power_W: 63mW; TempCo: 100 ppm/C; Value_Code: 5k90; Value: 5.90k; EIA_Code: E96; Res_ohm: 5.9k; SizeX_mm: 1; SizeY_mm: 0.5; SizeZ_mm: 0.6; Value2: 0.063W; AEC Qualified: Y; VDC_V: 50V; AEC Category: Q200; AEC Grade: 0
R48 = CMP-0026449-2: RES, 54.9 k, 1%, 0.063 W, AEC-Q200 Grade 0, 0402; Manufacturer: Vishay-Dale; Power_W: 63mW; TempCo: 100 ppm/C; Value_Code: 54k9; Value: 54.9k; EIA_Code: E96; SizeX_mm: 1; SizeY_mm: 0.5; SizeZ_mm: 0.6; Value2: 0.063W; AEC Qualified: Y; VDC_V: 50V; AEC Category: Q200; AEC Grade: 0
R104 R105 = CMP-0026992-3: RES, 0, 5%, 0.1 W, AEC-Q200 Grade 0, 0402; Manufacturer: Panasonic; Power_W: 100mW; TempCo: 600 ppm/C; Value_Code: 0000; Value: 0; EIA_Code: E24; SizeX_mm: 1; SizeY_mm: 0.5; SizeZ_mm: 0.6; Value2: 0.1W; CompType: Resistor; AEC Qualified: Y; VDC_V: 50V; AEC Category: Q200; SizeAreaWB_mm2: 3
T1 = CMP-0084630-1: Transformer, 400 uH, SMT; Manufacturer: Wurth Elektronik; Ind_H: 400µH; SizeY_mm: 12.9; SizeZ_mm: 6.2; Ns1toNp: 0.08; AEC Category: Q200; Value: 400uH; Lp: 400; Rsec3_ohm: 0.03; LeakageInd_H: 4µH; AEC Qualified: N; DCR_ohm: 1.1; SizeX_mm: 13; SizeAreaWB_mm2: 223.5; SizeArea_mm2: 167.7
TP4 TP5 TP14 = CMP-0055139-1: Test Point, Miniature, White, TH; Manufacturer: Keystone; PartNumber: 5002; CNHeader: FALSE; Green_Lifecycle: Active; Green_REACh: Passed; ContactFinish: Silver; CT: TRUE
TP6 TP7 = CMP-0055140-1: Test Point, Miniature, Orange, TH; Manufacturer: Keystone; PartNumber: 5003; CNHeader: FALSE; Green_Lifecycle: Active; Green_REACh: Passed; ContactFinish: Silver; CT: TRUE
TP8 TP10 TP11 = CMP-0055137-1: Test Point, Miniature, Red, TH; Manufacturer: Keystone; PartNumber: 5000; CNHeader: FALSE; Green_Lifecycle: Active; Green_REACh: Passed; ContactFinish: Silver; CT: TRUE
TP9 TP12 TP13 = CMP-0055138-1: Test Point, Miniature, Black, TH; Manufacturer: Keystone; PartNumber: 5001; CNHeader: FALSE; Green_Lifecycle: Active; Green_REACh: Passed; ContactFinish: Silver; CT: TRUE
U7 = CMP-0065788-2: Level-Translating I2C Bus Repeater, DGK0008A (VSSOP-8); Alternate Manufacturer: Texas Instruments; SizeAreaWB_mm2: 23.6; SizeZ_mm: 1.1; SizeX_mm: 4.9; SizeY_mm: 3; SizeArea_mm2: 14.7; CompType: IC; AEC Category: Q200; AEC Qualified: N
U8 = CMP-0032952-1: Low Voltage Adjustable Precision Shunt Regulator, 39 ppm / degC, 15 mA, -40 to 85 degC, 5-pin SOT-23 (DBV), Green (RoHS & no Sb/Br); Manufacturer: Texas Instruments; Initial Accuracy @ 25/deg C(%): 1; Min Iz for Regulation(uA): 80; VO Adj(Min)(V): 1.24; VO Adj(Max)(V): 6; SubFamily: Shunt Voltage Reference; Temp Coeff(Max)(ppm/ degree C): 129; Temp Coeff(Typ)(ppm/ degree C): 39; Rating: Catalog; Iout/Iz(Max)(mA): 15
U9 U11 = CMP-0074273-2: Low Quiescent Current, 1% Accurate Supervisor with Programmable-Delay, DSE0006A (WSON-6); Alternate PartNumber: TPS389001DSET; Alternate Manufacturer: Texas Instruments; SizeAreaWB_mm2: 6.25; U/M: EA; SizeZ_mm: 0.8; SizeX_mm: 1.5; SizeArea_mm2: 2.25; CompType: IC
U10 U12 = CMP-0006165-3: Optocoupler, 5 kV, 300-600% CTR, SMT; Manufacturer: Fairchild Semiconductor; CTR (Max): 600%; CTR (Min): 300%; Voltage_Isolation_Vrms: 5kV
U13 = CMP-0066105-1: 13-100V Wide Vin, Current Mode PWM Boost Controller, DGS0010A (VSSOP-10); Alternate Manufacturer: Texas Instruments; Green_Lifecycle: Active; SizeAreaWB_mm2: 23.6; Green_REACh: Passed; U/M: EA; SizeZ_mm: 1.1; SizeX_mm: 4.9; SizeY_mm: 3.0; SizeArea_mm2: 14.7; CompType: IC
U14 = CMP-0035942-1: Single Output LDO, 50 mA, Adjustable 1.175 to 90 V Output, 7 to 100 V Input, 8-pin MSOP (DGN), -40 to 125 degC, Green (RoHS & no Sb/Br); Manufacturer: Texas Instruments; Vdo(Typ)(mV): 290; Accuracy(%): 2.5; Iq(Typ)(mA): 0.02; Vin(Min)(V): 7; SubFamily: Single Channel LDO; Vin(Max)(V): 100; Vout Adj(Min)(V): 1.2; Vout Adj(Max)(V): 90; Iout(Max)(A): 0.05
U15 = CMP-0006164-3: Optocoupler, 3.75 kV, 80-160% CTR, SMT; Manufacturer: Fairchild Semiconductor; CTR (Max): 160%; SizeAreaWB_mm2: 4; CTR (Min): 80%; SizeZ_mm: 1; Voltage_Isolation_Vrms: 3.75kV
